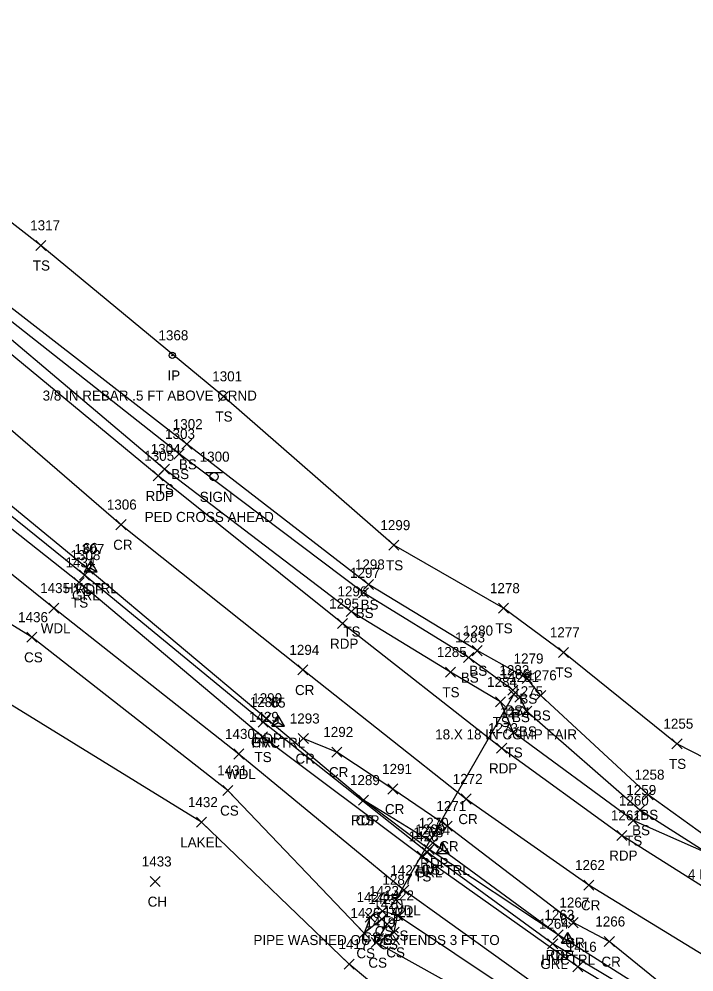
# Model space of a CAD drawing. Extents: x 1401404 to 1403982, y 557481 to 559873.
# Drawn here: x 1403136.9 to 1403271.2, y 558637.9 to 558827.6 of the extents above; entities that cross this region are included whole.
import ezdxf

# ---------------------------------------------------------------- set-up
doc = ezdxf.new("R2010")
doc.units = 0
for name, color, linetype in [('C_A', 7, 'Continuous'), ('C_I', 7, 'Continuous'), ('CPSM', 7, 'Continuous'), ('D_A', 7, 'Continuous'), ('D_C', 7, 'Continuous'), ('D_I', 7, 'Continuous'), ('D_TIC', 7, 'Continuous'), ('DCP', 7, 'Continuous'), ('L_A', 7, 'Continuous'), ('L_I', 7, 'Continuous'), ('L_TIC', 7, 'Continuous'), ('LAWA', 7, 'Continuous'), ('LAWE', 7, 'Continuous'), ('LELB', 7, 'Continuous'), ('M_A', 7, 'Continuous'), ('M_C', 7, 'Continuous'), ('M_I', 7, 'Continuous'), ('MPIR', 7, 'Continuous'), ('P_A', 7, 'Continuous'), ('P_I', 7, 'Continuous'), ('P_TIC', 7, 'Continuous'), ('PET', 7, 'Continuous'), ('PRC', 7, 'Continuous'), ('R_A', 7, 'Continuous'), ('R_I', 7, 'Continuous'), ('R_TIC', 7, 'Continuous'), ('RGR', 7, 'Continuous'), ('S_A', 7, 'Continuous'), ('S_C', 7, 'Continuous'), ('S_I', 7, 'Continuous'), ('SSGN', 7, 'Continuous'), ('U_C', 7, 'Continuous')]:
    doc.layers.add(name, color=color, linetype=linetype)

msp = doc.modelspace()

# ---------------------------------------------------------------- linework, layer by layer
at = {"layer": 'CPSM'}
for p, q in [((1403149.88, 558717.59), (1403151.13, 558719.76)), ((1403152.38, 558717.59), (1403151.13, 558719.76)), ((1403151.13, 558718.32), (1403151.13, 558719.76)), ((1403149.88, 558717.59), (1403151.13, 558718.32)), ((1403149.88, 558717.59), (1403152.38, 558717.59)), ((1403151.13, 558718.32), (1403151.13, 558718.32)), ((1403151.13, 558718.32), (1403152.38, 558717.59)), ((1403187.2, 558686.82), (1403188.45, 558688.99)), ((1403189.7, 558686.82), (1403188.45, 558688.99)), ((1403188.45, 558687.55), (1403188.45, 558688.99)), ((1403187.2, 558686.82), (1403188.45, 558687.55)), ((1403188.45, 558687.55), (1403188.45, 558687.55)), ((1403188.45, 558687.55), (1403189.7, 558686.82)), ((1403187.2, 558686.82), (1403189.7, 558686.82)), ((1403219.97, 558661.48), (1403221.22, 558663.64)), ((1403219.97, 558661.48), (1403221.22, 558662.2)), ((1403222.47, 558661.48), (1403221.22, 558663.64)), ((1403221.22, 558662.2), (1403221.22, 558663.64)), ((1403221.22, 558662.2), (1403221.22, 558662.2)), ((1403221.22, 558662.2), (1403222.47, 558661.48)), ((1403219.97, 558661.48), (1403222.47, 558661.48)), ((1403244.89, 558643.65), (1403246.14, 558645.81)), ((1403247.39, 558643.65), (1403246.14, 558645.81)), ((1403246.14, 558644.37), (1403246.14, 558645.81)), ((1403244.89, 558643.65), (1403246.14, 558644.37)), ((1403244.89, 558643.65), (1403247.39, 558643.65)), ((1403246.14, 558644.37), (1403246.14, 558644.37)), ((1403246.14, 558644.37), (1403247.39, 558643.65))]:
    msp.add_line(p, q, dxfattribs=at)
at = {"layer": 'D_TIC'}
for points in [[(1403234.37, 558692.22), (1403236.37, 558694.22)], [(1403236.37, 558692.22), (1403234.37, 558694.22)], [(1403210.89, 558651.28), (1403212.89, 558653.28)], [(1403212.89, 558651.28), (1403210.89, 558653.28)]]:
    msp.add_lwpolyline(points, dxfattribs=at)
at = {"layer": 'DCP'}
msp.add_lwpolyline([(1403235.37, 558693.22), (1403211.89, 558652.28)], dxfattribs=at)
at = {"layer": 'L_TIC'}
for points in [[(1403140.19, 558781.55), (1403142.19, 558783.55)], [(1403142.19, 558781.55), (1403140.19, 558783.55)], [(1403176.53, 558751.49), (1403178.53, 558753.49)], [(1403178.53, 558751.49), (1403176.53, 558753.49)], [(1403169.23, 558741.97), (1403171.23, 558743.97)], [(1403171.23, 558741.97), (1403169.23, 558743.97)], [(1403167.7, 558740.03), (1403169.7, 558742.03)], [(1403169.7, 558740.03), (1403167.7, 558742.03)], [(1403164.84, 558737.03), (1403166.84, 558739.03)], [(1403166.84, 558737.03), (1403164.84, 558739.03)], [(1403210.5, 558721.87), (1403212.5, 558723.87)], [(1403212.5, 558721.87), (1403210.5, 558723.87)], [(1403147.79, 558714.46), (1403149.79, 558716.46)], [(1403149.79, 558714.46), (1403147.79, 558716.46)], [(1403205.41, 558714.04), (1403207.41, 558716.04)], [(1403207.41, 558714.04), (1403205.41, 558716.04)], [(1403204.44, 558712.37), (1403206.44, 558714.37)], [(1403206.44, 558712.37), (1403204.44, 558714.37)], [(1403142.75, 558709.34), (1403144.75, 558711.34)], [(1403144.75, 558709.34), (1403142.75, 558711.34)], [(1403202.01, 558708.69), (1403204.01, 558710.69)], [(1403204.01, 558708.69), (1403202.01, 558710.69)], [(1403232.3, 558709.32), (1403234.3, 558711.32)], [(1403234.3, 558709.32), (1403232.3, 558711.32)], [(1403138.41, 558703.55), (1403140.41, 558705.55)], [(1403140.41, 558703.55), (1403138.41, 558705.55)], [(1403227.06, 558700.88), (1403229.06, 558702.88)], [(1403229.06, 558700.88), (1403227.06, 558702.88)], [(1403244.23, 558700.54), (1403246.23, 558702.54)], [(1403246.23, 558700.54), (1403244.23, 558702.54)], [(1403225.37, 558699.51), (1403227.37, 558701.51)], [(1403227.37, 558699.51), (1403225.37, 558701.51)], [(1403221.73, 558696.61), (1403223.73, 558698.61)], [(1403223.73, 558696.61), (1403221.73, 558698.61)], [(1403237.02, 558695.32), (1403239.02, 558697.32)], [(1403239.02, 558695.32), (1403237.02, 558697.32)], [(1403234.19, 558692.99), (1403236.19, 558694.99)], [(1403236.19, 558692.99), (1403234.19, 558694.99)], [(1403231.73, 558690.67), (1403233.73, 558692.67)], [(1403233.73, 558690.67), (1403231.73, 558692.67)], [(1403235.56, 558691.65), (1403237.56, 558693.65)], [(1403237.56, 558691.65), (1403235.56, 558693.65)], [(1403239.71, 558691.98), (1403241.71, 558693.98)], [(1403241.71, 558691.98), (1403239.71, 558693.98)], [(1403236.93, 558688.8), (1403238.93, 558690.8)], [(1403238.93, 558688.8), (1403236.93, 558690.8)], [(1403184.33, 558683.7), (1403186.33, 558685.7)], [(1403186.33, 558683.7), (1403184.33, 558685.7)], [(1403234.32, 558684.62), (1403236.32, 558686.62)], [(1403236.32, 558684.62), (1403234.32, 558686.62)], [(1403266.85, 558682.34), (1403268.85, 558684.34)], [(1403268.85, 558682.34), (1403266.85, 558684.34)], [(1403266.85, 558682.34), (1403268.85, 558684.34)], [(1403268.85, 558682.34), (1403266.85, 558684.34)], [(1403179.64, 558680.31), (1403181.64, 558682.31)], [(1403181.64, 558680.31), (1403179.64, 558682.31)], [(1403177.43, 558673.04), (1403179.43, 558675.04)], [(1403179.43, 558673.04), (1403177.43, 558675.04)], [(1403261.1, 558672.2), (1403263.1, 558674.2)], [(1403263.1, 558672.2), (1403261.1, 558674.2)], [(1403204.44, 558671.12), (1403206.44, 558673.12)], [(1403206.44, 558671.12), (1403204.44, 558673.12)], [(1403259.47, 558669.14), (1403261.47, 558671.14)], [(1403261.47, 558669.14), (1403259.47, 558671.14)], [(1403172.17, 558666.73), (1403174.17, 558668.73)], [(1403174.17, 558666.73), (1403172.17, 558668.73)], [(1403258.11, 558667.05), (1403260.11, 558669.05)], [(1403260.11, 558667.05), (1403258.11, 558669.05)], [(1403217.49, 558661.3), (1403219.49, 558663.3)], [(1403219.49, 558661.3), (1403217.49, 558663.3)], [(1403216.12, 558659.94), (1403218.12, 558661.94)], [(1403218.12, 558659.94), (1403216.12, 558661.94)], [(1403162.97, 558654.92), (1403164.97, 558656.92)], [(1403164.97, 558654.92), (1403162.97, 558656.92)], [(1403212.48, 558653.18), (1403214.48, 558655.18)], [(1403214.48, 558653.18), (1403212.48, 558655.18)], [(1403208.23, 558649.04), (1403210.23, 558651.04)], [(1403210.23, 558649.04), (1403208.23, 558651.04)], [(1403205.75, 558647.82), (1403207.75, 558649.82)], [(1403207.75, 558647.82), (1403205.75, 558649.82)], [(1403208.07, 558647.44), (1403210.07, 558649.44)], [(1403210.07, 558647.44), (1403208.07, 558649.44)], [(1403211.22, 558648.17), (1403213.22, 558650.17)], [(1403213.22, 558648.17), (1403211.22, 558650.17)], [(1403209.15, 558646.44), (1403211.15, 558648.44)], [(1403211.15, 558646.44), (1403209.15, 558648.44)], [(1403204.58, 558644.65), (1403206.58, 558646.65)], [(1403206.58, 558644.65), (1403204.58, 558646.65)], [(1403204.58, 558644.65), (1403206.58, 558646.65)], [(1403206.58, 558644.65), (1403204.58, 558646.65)], [(1403210.52, 558644.82), (1403212.52, 558646.82)], [(1403212.52, 558644.82), (1403210.52, 558646.82)], [(1403243.19, 558644.3), (1403245.19, 558646.3)], [(1403245.19, 558644.3), (1403243.19, 558646.3)], [(1403206.96, 558642.77), (1403208.96, 558644.77)], [(1403208.96, 558642.77), (1403206.96, 558644.77)], [(1403206.96, 558642.77), (1403208.96, 558644.77)], [(1403208.96, 558642.77), (1403206.96, 558644.77)], [(1403201.57, 558638.47), (1403203.57, 558640.47)], [(1403203.57, 558638.47), (1403201.57, 558640.47)], [(1403247.09, 558637.93), (1403249.09, 558639.93)], [(1403249.09, 558637.93), (1403247.09, 558639.93)]]:
    msp.add_lwpolyline(points, dxfattribs=at)
at = {"layer": 'LAWA'}
msp.add_lwpolyline([(1403316.66, 558597.36), (1403281.73, 558613.91), (1403272.54, 558615.21), (1403248.23, 558629.23), (1403213.48, 558654.18), (1403180.64, 558681.31), (1403143.75, 558710.34), (1403107.91, 558739.1), (1403071.69, 558772.58), (1403068.31, 558766.93), (1403071.88, 558756.66), (1403070.51, 558749.44)], dxfattribs=at)
at = {"layer": 'LAWE'}
msp.add_lwpolyline([(1403238.68, 558611.56), (1403231.81, 558615.04), (1403202.57, 558639.47), (1403173.17, 558667.73), (1403127.98, 558695.57), (1403090.18, 558721.43), (1403068.99, 558749.07), (1403055.64, 558748.74), (1403047.53, 558763.16), (1403042.82, 558768.94)], dxfattribs=at)
at = {"layer": 'LELB'}
for points in [[(1403267.85, 558683.34), (1403245.23, 558701.54), (1403233.3, 558710.32), (1403211.5, 558722.87), (1403177.53, 558752.49), (1403141.19, 558782.55), (1403104.69, 558810.96), (1403093.03, 558820.63), (1403082.17, 558826.69)], [(1403274.01, 558661.52), (1403275.4, 558663.64), (1403262.1, 558673.2), (1403240.71, 558692.98), (1403238.02, 558696.32), (1403228.06, 558701.88), (1403206.41, 558715.04), (1403170.23, 558742.97), (1403133.19, 558771.75), (1403094.93, 558802.64), (1403083.69, 558810.62), (1403082.17, 558826.69)], [(1403274.01, 558661.52), (1403260.47, 558670.14), (1403237.93, 558689.8), (1403236.56, 558692.65), (1403235.19, 558693.99), (1403226.37, 558700.51), (1403205.44, 558713.37), (1403168.7, 558741.03), (1403131.9, 558770.06), (1403093.4, 558800.92), (1403083.69, 558810.62)], [(1403274.01, 558661.52), (1403259.11, 558668.05), (1403235.32, 558685.62), (1403232.73, 558691.67), (1403222.73, 558697.61), (1403203.01, 558709.69), (1403165.84, 558738.03), (1403130.55, 558767.76), (1403091.61, 558799.16), (1403082.35, 558808.67)], [(1403567.19, 558568.67), (1403521.33, 558570.05), (1403484.77, 558571.48), (1403436.83, 558574.71), (1403390.35, 558579.88), (1403360.17, 558585.19), (1403345.93, 558587.28), (1403333.51, 558592.26), (1403317.51, 558600.62), (1403299, 558608.83), (1403282.94, 558617.97), (1403248.09, 558638.93), (1403217.12, 558660.94), (1403185.33, 558684.7), (1403148.79, 558715.46), (1403112.06, 558744.49), (1403074.23, 558776.66), (1403055.65, 558783.75), (1403043.18, 558796.21), (1403041.06, 558801.07)], [(1403270.93, 558606.4), (1403261.72, 558609.88), (1403247.68, 558621.68), (1403207.96, 558643.77), (1403210.15, 558647.44), (1403209.07, 558648.44), (1403205.58, 558645.65), (1403178.43, 558674.04), (1403139.41, 558704.55), (1403100.63, 558728.29)], [(1403322.92, 558653.73), (1403316.93, 558653.96), (1403307.14, 558661.3), (1403297.61, 558669.92), (1403279.38, 558677.44), (1403267.85, 558683.34)], [(1403244.19, 558645.3), (1403218.49, 558662.3), (1403205.44, 558672.12)], [(1403207.96, 558643.77), (1403211.52, 558645.82), (1403212.22, 558649.17), (1403209.23, 558650.04), (1403206.75, 558648.82), (1403205.58, 558645.65)], [(1403246.67, 558626.12), (1403212.22, 558649.17)]]:
    msp.add_lwpolyline(points, dxfattribs=at)
at = {"layer": 'MPIR'}
for radius in [0.625, 0.0833]:
    msp.add_circle((1403167.35, 558760.66), radius, dxfattribs=at)
at = {"layer": 'P_TIC'}
for points in [[(1403163.55, 558735.67), (1403165.55, 558737.67)], [(1403165.55, 558735.67), (1403163.55, 558737.67)], [(1403156.15, 558725.96), (1403158.15, 558727.96)], [(1403158.15, 558725.96), (1403156.15, 558727.96)], [(1403149.64, 558717.11), (1403151.64, 558719.11)], [(1403151.64, 558717.11), (1403149.64, 558719.11)], [(1403200.28, 558706.26), (1403202.28, 558708.26)], [(1403202.28, 558706.26), (1403200.28, 558708.26)], [(1403192.37, 558697.04), (1403194.37, 558699.04)], [(1403194.37, 558697.04), (1403192.37, 558699.04)], [(1403185.06, 558687.41), (1403187.06, 558689.41)], [(1403187.06, 558687.41), (1403185.06, 558689.41)], [(1403192.45, 558683.38), (1403194.45, 558685.38)], [(1403194.45, 558683.38), (1403192.45, 558685.38)], [(1403231.94, 558681.45), (1403233.94, 558683.45)], [(1403233.94, 558681.45), (1403231.94, 558683.45)], [(1403199.12, 558680.7), (1403201.12, 558682.7)], [(1403201.12, 558680.7), (1403199.12, 558682.7)], [(1403210.27, 558673.34), (1403212.27, 558675.34)], [(1403212.27, 558673.34), (1403210.27, 558675.34)], [(1403204.44, 558671.12), (1403206.44, 558673.12)], [(1403206.44, 558671.12), (1403204.44, 558673.12)], [(1403224.89, 558671.35), (1403226.89, 558673.35)], [(1403226.89, 558671.35), (1403224.89, 558673.35)], [(1403221.07, 558665.96), (1403223.07, 558667.96)], [(1403223.07, 558665.96), (1403221.07, 558667.96)], [(1403255.86, 558664.1), (1403257.86, 558666.1)], [(1403257.86, 558664.1), (1403255.86, 558666.1)], [(1403218.22, 558662.61), (1403220.22, 558664.61)], [(1403220.22, 558662.61), (1403218.22, 558664.61)], [(1403249.3, 558654.21), (1403251.3, 558656.21)], [(1403251.3, 558654.21), (1403249.3, 558656.21)], [(1403246.18, 558646.74), (1403248.18, 558648.74)], [(1403248.18, 558646.74), (1403246.18, 558648.74)], [(1403243.19, 558644.3), (1403245.19, 558646.3)], [(1403245.19, 558644.3), (1403243.19, 558646.3)], [(1403253.38, 558642.97), (1403255.38, 558644.97)], [(1403255.38, 558642.97), (1403253.38, 558644.97)]]:
    msp.add_lwpolyline(points, dxfattribs=at)
at = {"layer": 'PET'}
for points in [[(1403567.32, 558571.16), (1403521.05, 558571.89), (1403485.08, 558573.95), (1403437.34, 558577.29), (1403390.93, 558583.55), (1403361.61, 558591.03), (1403321.82, 558602.54), (1403283.74, 558620.33), (1403244.19, 558645.3), (1403219.22, 558663.61), (1403205.44, 558672.12), (1403186.06, 558688.41), (1403150.64, 558718.11), (1403114.18, 558748.06), (1403076.2, 558780.03), (1403043.94, 558806.7), (1402997.13, 558841.77), (1402954.25, 558870.69), (1402915.87, 558893.53), (1402876.18, 558915.42), (1402801.33, 558955.21), (1402766.49, 558972.95)], [(1403552.49, 558594.8), (1403524.49, 558596.02), (1403520.25, 558595.63), (1403487.06, 558596.83), (1403440.08, 558600.18), (1403395.05, 558605.77), (1403363.07, 558611.97), (1403293.66, 558643.04), (1403283.54, 558648.26), (1403256.86, 558665.1), (1403232.94, 558682.45), (1403201.28, 558707.26), (1403164.55, 558736.67), (1403129.25, 558765.78)]]:
    msp.add_lwpolyline(points, dxfattribs=at)
at = {"layer": 'PRC'}
for points in [[(1403567.87, 558582.77), (1403521.72, 558584.55), (1403486.23, 558585.01), (1403438.97, 558588.43), (1403393.1, 558594.9), (1403360.83, 558602.71), (1403288.92, 558631.6), (1403250.3, 558655.21), (1403225.89, 558672.35), (1403193.37, 558698.04), (1403157.15, 558726.96), (1403121.95, 558757.26), (1403083.22, 558789.98), (1403051.1, 558815.94), (1403004.27, 558851.49), (1402960.21, 558880.82), (1402921.63, 558903.82), (1402881.32, 558926.06), (1402807.32, 558964.73), (1402770.83, 558983.44)], [(1403270.51, 558630.83), (1403254.38, 558643.97), (1403247.18, 558647.74), (1403222.07, 558666.96), (1403211.27, 558674.34), (1403200.12, 558681.7), (1403193.45, 558684.38)]]:
    msp.add_lwpolyline(points, dxfattribs=at)
at = {"layer": 'R_TIC'}
for points in [[(1403148.87, 558715.9), (1403150.87, 558717.9)], [(1403150.87, 558715.9), (1403148.87, 558717.9)], [(1403184.48, 558686.65), (1403186.48, 558688.65)], [(1403186.48, 558686.65), (1403184.48, 558688.65)], [(1403217.12, 558660.74), (1403219.12, 558662.74)], [(1403219.12, 558660.74), (1403217.12, 558662.74)], [(1403242.1, 558642.52), (1403244.1, 558644.52)], [(1403244.1, 558642.52), (1403242.1, 558644.52)]]:
    msp.add_lwpolyline(points, dxfattribs=at)
at = {"layer": 'RGR'}
msp.add_lwpolyline([(1403343.04, 558588.83), (1403321.63, 558601.07), (1403283.23, 558619.58), (1403243.1, 558643.52), (1403218.12, 558661.74), (1403185.48, 558687.65), (1403149.87, 558716.9), (1403113.35, 558746.32), (1403075.03, 558778.37), (1403064.92, 558785.89), (1403057.13, 558787.17)], dxfattribs=at)
at = {"layer": 'SSGN'}
for p, q in [((1403174.05, 558737.36), (1403177.38, 558737.36)), ((1403175.69, 558736.52), (1403175.69, 558736.52))]:
    msp.add_line(p, q, dxfattribs=at)
msp.add_circle((1403175.69, 558736.52), 0.833, dxfattribs=at)

# ---------------------------------------------------------------- texts
at = {"layer": 'C_A'}
for p in [(1403145.82, 558713.32), (1403183.14, 558682.55), (1403215.91, 558657.2), (1403240.83, 558639.37)]:
    msp.add_text('HVCTRL', height=2, dxfattribs=at).set_placement(p)
at = {"layer": 'C_I'}
for s, p in [('66', (1403149.56, 558721.32)), ('65', (1403186.94, 558690.55)), ('64', (1403219.71, 558665.2)), ('63', (1403244.63, 558647.37))]:
    msp.add_text(s, height=2, dxfattribs=at).set_placement(p)
at = {"layer": 'D_A'}
for p in [(1403234.75, 558688.22), (1403211.27, 558647.28)]:
    msp.add_text('P', height=2, dxfattribs=at).set_placement(p)
at = {"layer": 'D_C'}
for s, p in [('18.X 18 IN CGMP FAIR', (1403219.71, 558684.22)), ('PIPE WASHED OUT EXTENDS 3 FT TO', (1403183.52, 558643.28))]:
    msp.add_text(s, height=2, dxfattribs=at).set_placement(p)
at = {"layer": 'D_I'}
for s, p in [('1286', (1403232.63, 558696.22)), ('1287', (1403209.2, 558655.28))]:
    msp.add_text(s, height=2, dxfattribs=at).set_placement(p)
at = {"layer": 'L_A'}
for s, p in [('TS', (1403139.6, 558777.55)), ('TS', (1403175.94, 558747.49)), ('BS', (1403168.67, 558737.97)), ('BS', (1403167.14, 558736.03)), ('TS', (1403164.25, 558733.03)), ('TS', (1403209.91, 558717.87)), ('TS', (1403147.2, 558710.46)), ('BS', (1403204.85, 558710.04)), ('BS', (1403203.88, 558708.37)), ('WDL', (1403141.17, 558705.34)), ('TS', (1403201.42, 558704.69)), ('TS', (1403231.71, 558705.32)), ('CS', (1403137.85, 558699.55)), ('BS', (1403226.5, 558696.88)), ('TS', (1403243.64, 558696.54)), ('BS', (1403224.81, 558695.51)), ('TS', (1403221.14, 558692.61)), ('BS', (1403236.46, 558691.32)), ('BS', (1403233.63, 558688.99)), ('BS', (1403235, 558687.65)), ('BS', (1403239.15, 558687.98)), ('TS', (1403231.14, 558686.67)), ('BS', (1403236.37, 558684.8)), ('TS', (1403183.73, 558679.7)), ('TS', (1403233.72, 558680.62)), ('TS', (1403266.26, 558678.34)), ('TS', (1403266.26, 558678.34)), ('WDL', (1403178.06, 558676.31)), ('CS', (1403176.88, 558669.04)), ('BS', (1403260.54, 558668.2)), ('CS', (1403203.88, 558667.12)), ('BS', (1403258.91, 558665.14)), ('LAKEL', (1403168.94, 558662.73)), ('TS', (1403257.52, 558663.05)), ('CS', (1403216.93, 558657.3)), ('TS', (1403215.53, 558655.94)), ('CH', (1403162.46, 558650.92)), ('WDL', (1403210.9, 558649.18)), ('CS', (1403207.67, 558645.04)), ('CS', (1403205.19, 558643.82)), ('CS', (1403207.51, 558643.44)), ('CS', (1403210.66, 558644.17)), ('CS', (1403208.59, 558642.44)), ('CS', (1403204.02, 558640.65)), ('CS', (1403204.02, 558640.65)), ('CS', (1403209.96, 558640.82)), ('CS', (1403242.63, 558640.3)), ('CS', (1403206.4, 558638.77)), ('CS', (1403206.4, 558638.77))]:
    msp.add_text(s, height=2, dxfattribs=at).set_placement(p)
at = {"layer": 'L_I'}
for s, p in [('1317', (1403139.07, 558785.55)), ('1301', (1403175.32, 558755.49)), ('1302', (1403167.46, 558745.97)), ('1303', (1403165.93, 558744.03)), ('1304', (1403163.07, 558741.03)), ('1299', (1403208.8, 558725.87)), ('1434', (1403146.1, 558718.46)), ('1298', (1403203.72, 558718.04)), ('1297', (1403202.75, 558716.37)), ('1435', (1403141.06, 558713.34)), ('1278', (1403230.61, 558713.32)), ('1296', (1403200.26, 558712.69)), ('1436', (1403136.66, 558707.55)), ('1280', (1403225.28, 558704.88)), ('1277', (1403242.54, 558704.54)), ('1283', (1403223.68, 558703.51)), ('1285', (1403220.04, 558700.61)), ('1279', (1403235.32, 558699.32)), ('1282', (1403232.49, 558696.99)), ('1284', (1403230.04, 558694.67)), ('1281', (1403234.43, 558695.65)), ('1276', (1403237.96, 558695.98)), ('1275', (1403235.24, 558692.8)), ('1274', (1403232.62, 558688.62)), ('1429', (1403182.62, 558687.7)), ('1255', (1403265.15, 558686.34)), ('1255', (1403265.15, 558686.34)), ('1430', (1403177.86, 558684.31)), ('1431', (1403176.31, 558677.04)), ('1258', (1403259.41, 558676.2)), ('1289', (1403202.74, 558675.12)), ('1259', (1403257.77, 558673.14)), ('1432', (1403170.48, 558670.73)), ('1260', (1403256.28, 558671.05)), ('1269', (1403215.74, 558665.3)), ('1428', (1403214.43, 558663.94)), ('1433', (1403161.28, 558658.92)), ('1427', (1403210.78, 558657.18)), ('1423', (1403206.54, 558653.04)), ('1424', (1403204.05, 558651.82)), ('1425', (1403206.37, 558651.44)), ('1422', (1403209.53, 558652.17)), ('1420', (1403207.37, 558650.44)), ('1421', (1403209.39, 558648.82)), ('1426', (1403202.83, 558648.65)), ('1426', (1403202.83, 558648.65)), ('1263', (1403241.45, 558648.3)), ('1419', (1403205.82, 558646.77)), ('1419', (1403205.82, 558646.77)), ('1417', (1403200.45, 558642.47)), ('1416', (1403245.91, 558641.93))]:
    msp.add_text(s, height=2, dxfattribs=at).set_placement(p)
at = {"layer": 'M_A'}
msp.add_text('IP', height=2, dxfattribs=at).set_placement((1403166.4, 558755.66))
at = {"layer": 'M_C'}
msp.add_text('3/8 IN REBAR .5 FT ABOVE GRND', height=2, dxfattribs=at).set_placement((1403141.55, 558751.66))
at = {"layer": 'M_I'}
msp.add_text('1368', height=2, dxfattribs=at).set_placement((1403164.61, 558763.66))
at = {"layer": 'P_A'}
for s, p in [('RDP', (1403162.04, 558731.67)), ('CR', (1403155.59, 558721.96)), ('RDP', (1403148.13, 558713.11)), ('RDP', (1403198.77, 558702.26)), ('CR', (1403191.8, 558693.04)), ('RDP', (1403183.54, 558683.41)), ('CR', (1403191.89, 558679.38)), ('RDP', (1403230.42, 558677.45)), ('CR', (1403198.56, 558676.7)), ('CR', (1403209.7, 558669.34)), ('RDP', (1403202.93, 558667.12)), ('CR', (1403224.32, 558667.35)), ('CR', (1403220.5, 558661.96)), ('RDP', (1403216.71, 558658.61)), ('RDP', (1403254.35, 558660.1)), ('CR', (1403248.73, 558650.21)), ('CR', (1403245.61, 558642.74)), ('RDP', (1403241.68, 558640.3)), ('CR', (1403252.81, 558638.97))]:
    msp.add_text(s, height=2, dxfattribs=at).set_placement(p)
at = {"layer": 'P_I'}
for s, p in [('1305', (1403161.78, 558739.67)), ('1306', (1403154.33, 558729.96)), ('1307', (1403147.87, 558721.11)), ('1295', (1403198.59, 558710.26)), ('1294', (1403190.68, 558701.04)), ('1290', (1403183.28, 558691.41)), ('1293', (1403190.76, 558687.38)), ('1273', (1403230.24, 558685.45)), ('1292', (1403197.43, 558684.7)), ('1291', (1403209.14, 558677.34)), ('1272', (1403223.2, 558675.35)), ('1289', (1403202.74, 558675.12)), ('1271', (1403219.94, 558669.96)), ('1261', (1403254.69, 558668.1)), ('1270', (1403216.44, 558666.61)), ('1262', (1403247.55, 558658.21)), ('1267', (1403244.44, 558650.74)), ('1263', (1403241.45, 558648.3)), ('1266', (1403251.59, 558646.97))]:
    msp.add_text(s, height=2, dxfattribs=at).set_placement(p)
at = {"layer": 'R_A'}
for p in [(1403147.41, 558711.9), (1403183.02, 558682.65), (1403215.66, 558656.74), (1403240.64, 558638.52)]:
    msp.add_text('GRL', height=2, dxfattribs=at).set_placement(p)
at = {"layer": 'R_I'}
for s, p in [('1308', (1403147.1, 558719.9)), ('1288', (1403182.78, 558690.65)), ('1268', (1403215.38, 558664.74)), ('1264', (1403240.36, 558646.52))]:
    msp.add_text(s, height=2, dxfattribs=at).set_placement(p)
at = {"layer": 'S_A'}
msp.add_text('SIGN', height=2, dxfattribs=at).set_placement((1403172.83, 558731.5))
at = {"layer": 'S_C'}
msp.add_text('PED CROSS AHEAD', height=2, dxfattribs=at).set_placement((1403161.87, 558727.5))
at = {"layer": 'S_I'}
msp.add_text('1300', height=2, dxfattribs=at).set_placement((1403172.82, 558739.5))
at = {"layer": 'U_C'}
msp.add_text('4 FT DIAM STEEL COVER (WELL?)', height=2, dxfattribs=at).set_placement((1403270.02, 558656.37))

doc.saveas('drawing.dxf')
